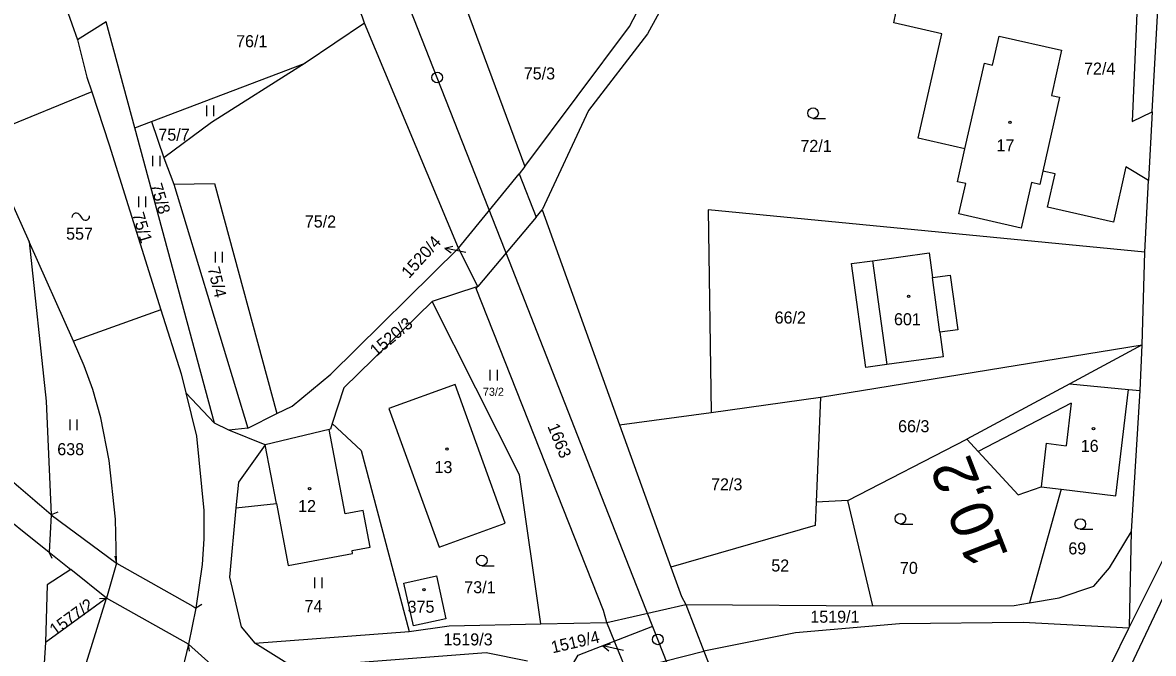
# Model space of a CAD drawing. Extents: x -553916 to -552953, y -1067469 to -1066637.
# Drawn here: x -553633.4 to -553473.7, y -1066907.3 to -1066818.1 of the extents above; entities that cross this region are included whole.
import ezdxf

# ---------------------------------------------------------------- set-up
doc = ezdxf.new("R2010")
doc.units = 0
for name, color, linetype in [('Hranice parcel', 7, 'Continuous'), ('Kolej', 7, 'Continuous'), ('Návěst místo trati', 7, 'Continuous'), ('Parcelní čísla', 7, 'Continuous'), ('Pop  PČ popisy', 7, 'Continuous'), ('Přejezd - štěrkové lože', 7, 'Continuous'), ('Vnitřní kresba', 7, 'Continuous'), ('Vrstva 1', 7, 'Continuous'), ('Vrstva 60', 7, 'Continuous'), ('Značky budov', 7, 'Continuous'), ('Značky kultur', 7, 'Continuous')]:
    doc.layers.add(name, color=color, linetype=linetype)

msp = doc.modelspace()

# ---------------------------------------------------------------- linework, layer by layer
at = {"layer": 'Hranice parcel'}
for p, q in [((-553473.84, -1066830.72), (-553472.63, -1066808.29)), ((-553621.6, -1066817.99), (-553625.66, -1066820.5)), ((-553617.57, -1066832.95), (-553621.6, -1066817.99)), ((-553585.12, -1066818.17), (-553593.5, -1066823.84)), ((-553615.21, -1066832.06), (-553593.5, -1066823.84)), ((-553623.67, -1066827.87), (-553637.71, -1066833.62)), ((-553476.7, -1066832.08), (-553473.84, -1066830.72)), ((-553473.84, -1066830.72), (-553474.36, -1066840.41)), ((-553617.57, -1066832.95), (-553615.21, -1066832.06)), ((-553615.21, -1066832.06), (-553613.46, -1066837.22)), ((-553606.33, -1066874.71), (-553617.57, -1066832.95)), ((-553613.46, -1066837.22), (-553612.07, -1066840.94)), ((-553474.36, -1066840.41), (-553477.57, -1066838.5)), ((-553474.91, -1066850.54), (-553474.36, -1066840.41)), ((-553612.07, -1066840.94), (-553601.6, -1066875.43)), ((-553474.91, -1066850.54), (-553536.59, -1066844.58)), ((-553536.59, -1066844.58), (-553536.15, -1066873.24)), ((-553626.26, -1066863.15), (-553632.51, -1066849.1)), ((-553475.25, -1066863.65), (-553474.91, -1066850.54)), ((-553569.13, -1066855.4), (-553575.56, -1066857.54)), ((-553613.88, -1066858.68), (-553626.26, -1066863.15)), ((-553520.71, -1066871.05), (-553475.25, -1066863.65)), ((-553475.55, -1066870.13), (-553475.25, -1066863.65)), ((-553610.38, -1066870.43), (-553606.33, -1066874.71)), ((-553476.78, -1066890.04), (-553475.55, -1066870.13)), ((-553536.15, -1066873.24), (-553520.71, -1066871.05)), ((-553520.71, -1066871.05), (-553521.33, -1066885.91)), ((-553601.6, -1066875.43), (-553597.49, -1066873.38)), ((-553549.09, -1066874.96), (-553536.15, -1066873.24)), ((-553604.31, -1066875.73), (-553606.33, -1066874.71)), ((-553601.6, -1066875.43), (-553604.31, -1066875.73)), ((-553599.14, -1066877.81), (-553604.31, -1066875.73)), ((-553590.14, -1066875.63), (-553599.14, -1066877.81)), ((-553516.84, -1066885.65), (-553500.06, -1066876.99)), ((-553629.4, -1066887.71), (-553637.93, -1066880.39)), ((-553486.72, -1066884.07), (-553491.17, -1066900.15)), ((-553516.84, -1066885.65), (-553521.33, -1066885.91)), ((-553513.34, -1066900.54), (-553516.84, -1066885.65)), ((-553629.4, -1066887.71), (-553620.15, -1066894.52)), ((-553477.08, -1066903.52), (-553476.78, -1066890.04)), ((-553620.15, -1066894.52), (-553621.57, -1066899.49)), ((-553621.57, -1066899.49), (-553626.61, -1066895.43)), ((-553621.57, -1066899.49), (-553630.21, -1066905.76)), ((-553624.88, -1066910.1), (-553621.57, -1066899.49)), ((-553539.74, -1066900.36), (-553513.34, -1066900.54)), ((-553600.63, -1066905.86), (-553578.83, -1066904.19)), ((-553560.24, -1066903.11), (-553550.91, -1066902.91)), ((-553477.16, -1066903.7), (-553477.08, -1066903.52)), ((-553630.21, -1066905.76), (-553632.98, -1066948.88)), ((-553591.81, -1066911.32), (-553600.63, -1066905.86)), ((-553610.01, -1066906), (-553611.35, -1066911.57))]:
    msp.add_line(p, q, dxfattribs=at)
for points in [[(-553477.08, -1066903.52), (-553471.25, -1066891.92), (-553468.41, -1066870.82), (-553466.8, -1066842.82), (-553465.31, -1066811.26), (-553449.58, -1066745.18), (-553421.6, -1066636.65)], [(-553562.46, -1066838.44), (-553547.69, -1066818.62), (-553535.38, -1066795.04), (-553519.42, -1066775.8), (-553495.28, -1066749.85), (-553495.01, -1066748.81)], [(-553643.88, -1066774.03), (-553635.29, -1066793.34), (-553625.66, -1066820.5)], [(-553532.8, -1066797.02), (-553545.17, -1066819.67), (-553553.48, -1066830.52), (-553560.01, -1066844.54)], [(-553483.73, -1066809.15), (-553480.88, -1066809.9), (-553479.9, -1066810.22), (-553478.34, -1066811.42), (-553477.07, -1066812.9), (-553475.95, -1066814.54), (-553476.7, -1066832.08)], [(-553500.33, -1066835.91), (-553506.92, -1066834.42), (-553503.58, -1066819.65), (-553510.37, -1066818.12), (-553510, -1066816.53), (-553512.88, -1066815.92), (-553511.82, -1066810.98), (-553508.93, -1066811.58), (-553508.63, -1066810.19), (-553503.64, -1066811.31)], [(-553625.66, -1066820.5), (-553624.36, -1066825.78), (-553623.67, -1066827.87)], [(-553500.33, -1066835.91), (-553497.54, -1066823.83), (-553496.39, -1066824.1), (-553495.45, -1066820), (-553486.65, -1066822), (-553488.1, -1066828.38), (-553486.94, -1066828.63), (-553489.31, -1066839.1)], [(-553593.5, -1066823.84), (-553606.76, -1066832.22), (-553613.46, -1066837.22)], [(-553623.67, -1066827.87), (-553621.18, -1066835.35), (-553613.88, -1066858.68)], [(-553637.71, -1066833.62), (-553635.67, -1066841.32), (-553635.29, -1066842.84), (-553632.51, -1066849.1)], [(-553489.31, -1066839.1), (-553489.74, -1066840.96), (-553490.91, -1066840.7), (-553492.37, -1066847.14), (-553501.19, -1066845.13), (-553500.2, -1066840.84), (-553501.37, -1066840.59), (-553500.33, -1066835.91)], [(-553477.57, -1066838.5), (-553479.33, -1066846.32), (-553488.66, -1066844.2), (-553487.56, -1066839.48), (-553489.31, -1066839.1)], [(-553612.07, -1066840.94), (-553606.31, -1066840.83), (-553597.49, -1066873.38)], [(-553632.51, -1066849.1), (-553630.08, -1066871.62), (-553629.4, -1066887.71)], [(-553597.49, -1066873.38), (-553595.36, -1066872.31), (-553589.9, -1066867.8), (-553571.83, -1066850)], [(-553513.37, -1066851.75), (-553505.38, -1066850.65), (-553504.9, -1066854.14), (-553502.39, -1066853.78), (-553501.32, -1066861.52), (-553503.85, -1066861.86), (-553503.37, -1066865.34), (-553511.35, -1066866.43), (-553514.32, -1066866.85), (-553516.34, -1066852.16), (-553513.37, -1066851.75)], [(-553575.56, -1066857.54), (-553588.06, -1066869.75), (-553589.68, -1066874.77)], [(-553560.24, -1066903.11), (-553563.23, -1066882.03), (-553575.56, -1066857.54)], [(-553613.88, -1066858.68), (-553611.04, -1066867.75), (-553610.38, -1066870.43)], [(-553620.15, -1066894.52), (-553620.3, -1066888.33), (-553621.19, -1066880.03), (-553622.36, -1066873.98), (-553623.5, -1066869.95), (-553624.71, -1066866.63), (-553626.26, -1066863.15)], [(-553475.25, -1066863.65), (-553485.48, -1066869.15), (-553500.06, -1066876.99)], [(-553610.38, -1066870.43), (-553608.88, -1066876.59), (-553607.84, -1066887.1), (-553607.82, -1066891.09), (-553608.06, -1066894.72), (-553608.96, -1066900.89), (-553610.01, -1066906)], [(-553572.34, -1066869.25), (-553581.7, -1066872.64), (-553574.6, -1066892.26), (-553565.24, -1066888.87), (-553572.34, -1066869.25)], [(-553486.72, -1066884.07), (-553478.97, -1066884.99), (-553477.19, -1066869.97), (-553475.55, -1066870.13)], [(-553589.68, -1066874.77), (-553589.94, -1066875.59), (-553590.14, -1066875.63)], [(-553589.68, -1066874.77), (-553585.58, -1066878.58), (-553578.83, -1066904.19)], [(-553603.29, -1066886.71), (-553597.57, -1066886.1), (-553595.9, -1066894.86), (-553586.82, -1066893.14), (-553586.89, -1066892.75), (-553584.34, -1066892.26), (-553585.34, -1066887.07), (-553587.88, -1066887.56), (-553590.14, -1066875.63)], [(-553500.06, -1066876.99), (-553498.46, -1066878.73), (-553492.8, -1066884.85), (-553489.55, -1066883.74), (-553486.72, -1066884.07)], [(-553599.14, -1066877.81), (-553602.95, -1066883.09), (-553603.29, -1066886.71)], [(-553638.51, -1066885.89), (-553629.69, -1066892.95), (-553626.61, -1066895.43)], [(-553603.29, -1066886.71), (-553604.22, -1066896.53), (-553602.56, -1066903.53), (-553600.63, -1066905.86)], [(-553521.33, -1066885.91), (-553521.47, -1066889.2), (-553541.86, -1066895.1)], [(-553491.17, -1066900.15), (-553486.99, -1066899.43), (-553482.1, -1066897.78), (-553479.9, -1066895.18), (-553476.78, -1066890.04)], [(-553468.58, -1066891.47), (-553477.31, -1066909.92), (-553483.75, -1066931.3), (-553489.9, -1066939.2)], [(-553626.61, -1066895.43), (-553629.94, -1066897.59), (-553630.21, -1066905.76)], [(-553578.22, -1066903.39), (-553579.56, -1066897.34), (-553574.98, -1066896.32), (-553573.63, -1066902.38), (-553578.22, -1066903.39)], [(-553513.34, -1066900.54), (-553493.34, -1066900.53), (-553491.17, -1066900.15)], [(-553578.83, -1066904.19), (-553573.18, -1066903.38), (-553560.24, -1066903.11)], [(-553477.16, -1066903.7), (-553492.06, -1066902.9), (-553509.55, -1066903.09), (-553524.22, -1066904.36), (-553537.18, -1066906.98)], [(-553515.05, -1066965.6), (-553502.53, -1066951.2), (-553486.22, -1066930.56), (-553479.63, -1066908.8), (-553477.16, -1066903.7)], [(-553580.85, -1066983.77), (-553580.5, -1066981.61), (-553581.9, -1066962.72), (-553586.71, -1066945.98), (-553600.4, -1066914.59), (-553610.01, -1066906)], [(-553562.08, -1066908.37), (-553567.96, -1066907.21), (-553588.75, -1066908.8), (-553591.81, -1066911.32)]]:
    msp.add_lwpolyline(points, dxfattribs=at)
at = {"layer": 'Kolej'}
msp.add_lwpolyline([(-553503.32, -1067065.81), (-553502.68, -1067054.03), (-553502.76, -1067041.5), (-553503.63, -1067029.06), (-553504.76, -1067019.97), (-553506.18, -1067011.39), (-553508.33, -1067001.39), (-553510.95, -1066991.62), (-553512.92, -1066985.29), (-553515.65, -1066977.35), (-553517.42, -1066972.53), (-553519.16, -1066967.95), (-553522.89, -1066958.38), (-553529.1, -1066942.55), (-553538.69, -1066918.11), (-553542.91, -1066907.33), (-553546.69, -1066897.68), (-553555.03, -1066876.44), (-553564.64, -1066851.89), (-553574.24, -1066827.43), (-553583.19, -1066804.62)], dxfattribs=at)
at = {"layer": 'Návěst místo trati'}
for centre in [(-553574.86, -1066825.84), (-553543.69, -1066905.31)]:
    msp.add_circle(centre, 0.75, dxfattribs=at)
at = {"layer": 'Pop  PČ popisy'}
for p, q in [((-553573.76, -1066849.96), (-553572.67, -1066849.68)), ((-553570.82, -1066850.59), (-553573.76, -1066849.96)), ((-553573.76, -1066849.96), (-553572.89, -1066850.66)), ((-553551.46, -1066906.23), (-553550.37, -1066905.95)), ((-553548.53, -1066906.86), (-553551.46, -1066906.23)), ((-553551.46, -1066906.23), (-553550.59, -1066906.93))]:
    msp.add_line(p, q, dxfattribs=at)
at = {"layer": 'Přejezd - štěrkové lože'}
msp.add_lwpolyline([(-553598.54, -1066929.82), (-553559.03, -1066914.56), (-553554.95, -1066907.55), (-553544.41, -1066903.46)], dxfattribs=at)
at = {"layer": 'Vnitřní kresba'}
for p, q in [((-553513.37, -1066851.75), (-553511.35, -1066866.43)), ((-553503.85, -1066861.86), (-553504.9, -1066854.14)), ((-553485.48, -1066869.15), (-553477.19, -1066869.97)), ((-553485.28, -1066871.92), (-553498.46, -1066878.73)), ((-553485.28, -1066871.92), (-553485.99, -1066877.92)), ((-553597.57, -1066886.1), (-553599.14, -1066877.81)), ((-553488.82, -1066877.58), (-553489.55, -1066883.74)), ((-553488.82, -1066877.58), (-553485.99, -1066877.92)), ((-553629.4, -1066887.71), (-553629.69, -1066892.95)), ((-553628.47, -1066887.34), (-553629.4, -1066887.71)), ((-553629.27, -1066893.86), (-553629.69, -1066892.95)), ((-553620.39, -1066893.55), (-553620.15, -1066894.52)), ((-553620.15, -1066894.52), (-553609.37, -1066900.63)), ((-553622.57, -1066899.52), (-553621.57, -1066899.49)), ((-553610.01, -1066906), (-553621.57, -1066899.49)), ((-553609.37, -1066900.63), (-553608.96, -1066900.89)), ((-553608.1, -1066900.38), (-553608.96, -1066900.89)), ((-553609.84, -1066906.99), (-553610.01, -1066906))]:
    msp.add_line(p, q, dxfattribs=at)
at = {"layer": 'Vrstva 1'}
for p, q in [((-553573.62, -1066808.38), (-553562.46, -1066838.44)), ((-553571.83, -1066850), (-553585.12, -1066818.17)), ((-553562.46, -1066838.44), (-553563.28, -1066839.45)), ((-553571.83, -1066850), (-553563.28, -1066839.45)), ((-553563.28, -1066839.45), (-553560.9, -1066845.6)), ((-553560.9, -1066845.6), (-553560.01, -1066844.54)), ((-553560.01, -1066844.54), (-553549.09, -1066874.96)), ((-553560.9, -1066845.6), (-553569.13, -1066855.4)), ((-553569.13, -1066855.4), (-553571.83, -1066850)), ((-553549.09, -1066874.96), (-553541.86, -1066895.1)), ((-553550.91, -1066902.91), (-553539.74, -1066900.36)), ((-553539.74, -1066900.36), (-553537.18, -1066906.98)), ((-553548.13, -1066909.75), (-553550.91, -1066902.91)), ((-553548.13, -1066909.75), (-553537.18, -1066906.98))]:
    msp.add_line(p, q, dxfattribs=at)
for points in [[(-553585.12, -1066818.17), (-553585.42, -1066817.3), (-553592.22, -1066799.8)], [(-553550.91, -1066902.91), (-553551.37, -1066901.2), (-553569.36, -1066855.68), (-553569.13, -1066855.4)], [(-553541.86, -1066895.1), (-553540.37, -1066899.25), (-553539.74, -1066900.36)], [(-553537.18, -1066906.98), (-553519.04, -1066953.03), (-553515.05, -1066965.6)]]:
    msp.add_lwpolyline(points, dxfattribs=at)
at = {"layer": 'Vrstva 60'}
msp.add_line((-553537.18, -1066906.98), (-553537.18, -1066906.98), dxfattribs=at)
at = {"layer": 'Značky budov'}
msp.add_line((-553625.36, -1066845.33), (-553625.06, -1066845.73), dxfattribs=at)
for centre in [(-553493.95, -1066832.18), (-553508.26, -1066856.8), (-553482.15, -1066875.51), (-553573.48, -1066878.39), (-553592.89, -1066884), (-553576.73, -1066898.27)]:
    msp.add_circle(centre, 0.175, dxfattribs=at)
for centre, start, end in [((-553625.87, -1066845.62), 29.2914, 181.2189), ((-553624.55, -1066845.44), 209.2914, 1.2189)]:
    msp.add_arc(centre, 0.588, start, end, dxfattribs=at)
at = {"layer": 'Značky kultur'}
for p, q in [((-553607.42, -1066831.3), (-553607.42, -1066829.8)), ((-553606.42, -1066831.3), (-553606.42, -1066829.8)), ((-553521.76, -1066831.63), (-553520.01, -1066831.63)), ((-553615.01, -1066838.4), (-553615.01, -1066836.9)), ((-553614.01, -1066838.4), (-553614.01, -1066836.9)), ((-553617.03, -1066844.16), (-553617.03, -1066842.66)), ((-553616.03, -1066844.16), (-553616.03, -1066842.66)), ((-553606.18, -1066852.02), (-553606.18, -1066850.52)), ((-553605.18, -1066852.02), (-553605.18, -1066850.52)), ((-553567.36, -1066868.69), (-553567.36, -1066867.19)), ((-553566.36, -1066868.69), (-553566.36, -1066867.19)), ((-553626.71, -1066875.71), (-553626.71, -1066874.21)), ((-553625.71, -1066875.71), (-553625.71, -1066874.21)), ((-553509.42, -1066888.99), (-553507.67, -1066888.99)), ((-553484.01, -1066889.74), (-553482.26, -1066889.74)), ((-553568.55, -1066894.9), (-553566.8, -1066894.9)), ((-553592.13, -1066898.07), (-553592.13, -1066896.57)), ((-553591.13, -1066898.07), (-553591.13, -1066896.57))]:
    msp.add_line(p, q, dxfattribs=at)
for centre in [(-553521.76, -1066830.88), (-553509.42, -1066888.24), (-553484.01, -1066888.99), (-553568.55, -1066894.15)]:
    msp.add_circle(centre, 0.75, dxfattribs=at)

# ---------------------------------------------------------------- texts
at = {"layer": 'Návěst místo trati'}
msp.add_text('10,2', height=6, rotation=111.2039, dxfattribs=at).set_placement((-553494.09, -1066893.45))
at = {"layer": 'Parcelní čísla'}
for s, height, p in [('76/1', 1.7, (-553603.27, -1066821.56)), ('75/3', 1.7, (-553562.63, -1066826.12)), ('72/4', 1.7, (-553483.48, -1066825.43)), ('75/7', 1.7, (-553614.25, -1066834.78)), ('72/1', 1.7, (-553523.55, -1066836.37)), ('17', 1.7, (-553495.86, -1066836.3)), ('75/2', 1.7, (-553593.56, -1066847.06)), ('557', 1.7, (-553627.28, -1066848.78)), ('66/2', 1.7, (-553527.19, -1066860.64)), ('601', 1.7, (-553510.33, -1066860.88)), ('73/2', 1.14, (-553568.4, -1066870.86)), ('66/3', 1.7, (-553509.75, -1066876.01)), ('16', 1.7, (-553483.95, -1066878.79)), ('638', 1.7, (-553628.53, -1066879.26)), ('13', 1.7, (-553575.24, -1066881.79)), ('72/3', 1.7, (-553536.17, -1066884.23)), ('12', 1.7, (-553594.51, -1066887.3)), ('69', 1.7, (-553485.7, -1066893.29)), ('52', 1.7, (-553527.66, -1066895.71)), ('70', 1.7, (-553509.49, -1066896.05)), ('73/1', 1.7, (-553571.03, -1066898.78)), ('74', 1.7, (-553593.59, -1066901.46)), ('375', 1.7, (-553579.04, -1066901.54)), ('1519/1', 1.7, (-553522.15, -1066902.95)), ('1519/3', 1.7, (-553573.98, -1066906.16))]:
    msp.add_text(s, height=height, dxfattribs=at).set_placement(p)
for s, rotation, p in [('75/8', 287, (-553615.42, -1066841.09)), ('75/1', 287, (-553617.97, -1066845.2)), ('75/4', 284, (-553607.31, -1066852.83)), ('1520/3', 40, (-553583.48, -1066865.39)), ('1577/2', 36, (-553628.84, -1066904.86))]:
    msp.add_text(s, height=1.7, rotation=rotation, dxfattribs=at).set_placement(p)
at = {"layer": 'Vrstva 1'}
for s, rotation, p in [('1520/4', 48, (-553578.83, -1066854.36)), ('1663', 292, (-553559.32, -1066875.16)), ('1519/4', 13, (-553558.56, -1066907.29))]:
    msp.add_text(s, height=1.7, rotation=rotation, dxfattribs=at).set_placement(p)

doc.saveas('drawing.dxf')
